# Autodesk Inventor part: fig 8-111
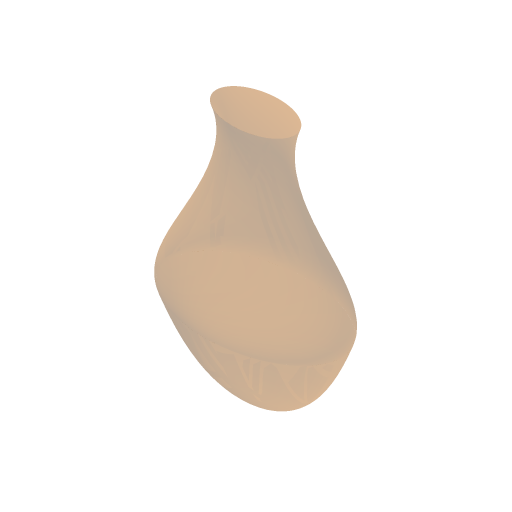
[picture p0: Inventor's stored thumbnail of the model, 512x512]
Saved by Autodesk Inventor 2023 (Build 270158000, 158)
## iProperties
Created: 2004-05
Part Number: fig 8-111
Document SubType Name: Modeling
Designer: CADCIM Technologies
Manufacturer: Standard
Standards Organization: Custom
Density: 1 g/cm^3
Material: Generic
Appearance: Default
Author: CADCIM Technologies
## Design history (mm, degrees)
sketch "Sketch4"
  geometry: 1 further point; 1 other entity
  constraints: 2 other
workplane "Work Plane2"
sketch "Sketch5"
  geometry: 1 further point; 1 other entity
  constraints: 2 other
feature "LoftSrf1" sketch "Sketch5" dims "d4" = 20, "d5" = 110 deg, "d6" = 40, "d7" = 70 deg
patch "Boundary Patch2" dims "d10" = 0, "d11" = 0
patch "Boundary Patch3" dims "d13" = 0, "d14" = 0
body "Srf1"
body "Srf3"
body "Srf4"
other parameters: "d3" = 33.5
